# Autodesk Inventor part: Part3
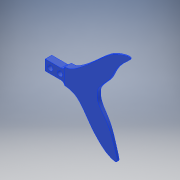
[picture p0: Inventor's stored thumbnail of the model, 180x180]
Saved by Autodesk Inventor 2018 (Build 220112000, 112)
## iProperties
Created: 2019-06
Part Number: Part3
Material: Generic
Document SubType Name: Modeling
Designer: multivac
Density: 1 g/cm^3
Appearance: Default
Author: multivac
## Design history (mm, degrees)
sketch "Sketch1"
  geometry: L1 (-91.707, 47.044)-(167.57, 47.044); L2 (167.57, 47.044)-(167.57, -120.177); L3 (167.57, -120.177)-(-91.707, -120.177); L4 (-91.707, -120.177)-(-91.707, 47.044); L5 (121.135, -26.774)-(124.192, -26.774); L6 (124.192, -26.774)-(126.865, -25.874); L7 (126.865, -25.874)-(134.346, -20.494); L8 (134.346, -20.494)-(142.94, -12.823); L9 (142.94, -12.823)-(147.62, -8.303); L10 (147.62, -8.303)-(153.986, -3.114); L11 (153.986, -3.114)-(157.392, -0.759); L12 (157.392, -0.759)-(165.191, 2.074); L13 (165.191, 2.074)-(168.66, 2.679); L14 (168.66, 2.679)-(169.806, 1.756); L15 (169.806, 1.756)-(169.138, 0.674); L16 (169.138, 0.674)-(162.358, -5.374); L17 (162.358, -5.374)-(158.665, -10.117); L18 (158.665, -10.117)-(155.737, -16.642); L19 (155.737, -16.642)-(153.859, -20.303); L20 (153.859, -20.303)-(147.683, -26.224); L21 (147.683, -26.224)-(144.787, -30.744); L22 (144.787, -30.744)-(144.787, -32.908); L23 (144.787, -32.908)-(144.787, -37.238); L24 (144.787, -37.238)-(146.346, -41.153); L25 (146.346, -41.153)-(151.408, -47.487); L26 (151.408, -47.487)-(154.559, -53.503); L27 (154.559, -53.503)-(157.774, -64.008); L28 (157.774, -64.008)-(159.365, -68.687); L29 (159.365, -68.687)-(159.907, -71.711); L30 (159.907, -71.711)-(158.442, -72.666); L31 (158.442, -72.666)-(153.158, -70.47); L32 (153.158, -70.47)-(149.211, -67.637); L33 (149.211, -67.637)-(141.985, -59.965); L34 (141.985, -59.965)-(137.147, -52.103); L35 (137.147, -52.103)-(132.118, -44.24); L36 (132.118, -44.24)-(127.438, -40.134); L37 (127.438, -40.134)-(121.135, -39.275); L38 (121.135, -26.774)-(121.135, -39.275); 1 further point; 1 other entity
  constraints: 3 vertical, 2 end point, 1 horizontal, 5 other
extrude "Extrusion1" new body sketch "Sketch1" distance "d13" = 5; taper "d14" = 0 deg
sketch "Sketch2"
  geometry: L1 (-121.135, 0)-(-121.135, 5) reference; L2 (-121.135, 5)-(-174.916, 2.5); L3 (-174.916, 2.5)-(-121.135, 0); 1 further point
  constraints: 4 end point
extrude "Extrusion2" sketch "Sketch2" distance "d16" = 80; taper "d18" = 0 deg; dims "d17" = 5, "d19" = 0
sketch "Sketch3"
  geometry: L1 (0, 6.25)-(0, 10.25); L2 (0, 6.25)-(4, 6.25); L3 (0, 10.25)-(5, 10.25); L4 (5, 10.25)-(5, 2.25); L5 (5, 12.5)-(5, 0) reference; L6 (5, 2.25)-(0, 2.25); L7 (0, 2.25)-(0, 6.25); L8 (0, 0)-(0, 12.5) reference; 1 further point
  constraints: 12 end point, 2 perpendicular, 1 collinear, 1 horizontal, 1 point on line
  dimensions: "d20" = 4 distance of L1.start L1.end; "d21" = 90 deg angle of L2 L1 (derived); "d22" = 8 distance of L3.end L4.end
extrude "Extrusion3" join sketch "Sketch3" distance "d23" = 15; taper "d24" = 0 deg
fillet "Fillet1" dims "d25" = 3
sketch "Sketch4"
  geometry: L1 (0, 0)-(0, 8) reference; C1 r 2 at (3.75, 4); C2 r 2 at (11.25, 4); 1 further point
  constraints: 2 centre point
  dimensions: "d28" = 4 diameter of C1; "d29" = 4 diameter of C2
extrude "Extrusion4" cut sketch "Sketch4" distance "d30" = 15; taper "d31" = 0 deg
body "Solid1"
node "Image1"
